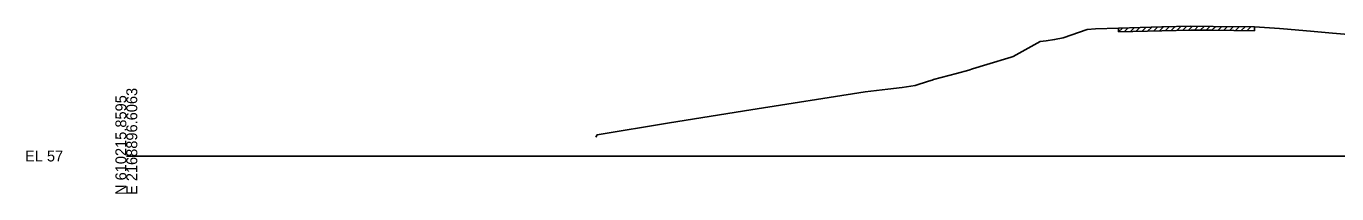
# Model space of a CAD drawing. Extents: x -26 to 6803, y -10 to 19606.
# Drawn here: x 1974.3 to 2310.6, y 12490.3 to 12533.3 of the extents above; entities that cross this region are included whole.
import ezdxf

# ---------------------------------------------------------------- set-up
doc = ezdxf.new("R2010")
doc.units = 0
for name, color, linetype in [('RD_GPK_XS_Cell', 7, 'Continuous'), ('RD_XS_ExGround', 7, 'Continuous'), ('RD_XS_ExPaveRet', 7, 'Continuous')]:
    doc.layers.add(name, color=color, linetype=linetype)

msp = doc.modelspace()

# ---------------------------------------------------------------- linework, layer by layer
at = {"layer": 'RD_GPK_XS_Cell'}
msp.add_line((2000, 12500), (2400, 12500), dxfattribs=at)
at = {"layer": 'RD_XS_ExGround'}
msp.add_lwpolyline([(2120.47, 12504.83), (2120.81, 12505.42), (2139.34, 12508.51), (2160.28, 12511.84), (2189.59, 12516.47), (2195.37, 12517.13), (2199.05, 12517.58), (2202.42, 12518.13), (2205.8, 12519.18), (2206.74, 12519.46), (2207.12, 12519.62), (2213.04, 12521.16), (2216.17, 12521.99), (2217.09, 12522.39), (2220.84, 12523.47), (2227.09, 12525.37), (2227.58, 12525.54), (2234.47, 12529.38), (2236.06, 12529.59), (2238.19, 12529.89), (2240.38, 12530.33), (2246.57, 12532.44), (2248.73, 12532.6), (2254.58, 12532.82), (2265.74, 12533.11), (2273.14, 12533.3), (2278.86, 12533.25), (2289.48, 12533.14), (2295.95, 12532.7), (2297.93, 12532.55), (2304.79, 12531.92), (2309.52, 12531.5), (2314.62, 12531.09)], dxfattribs=at)
at = {"layer": 'RD_XS_ExPaveRet'}
for p, q in [((2254.58, 12531.82), (2255.61, 12532.84)), ((2254.58, 12531.82), (2254.58, 12532.82)), ((2254.58, 12531.82), (2265.74, 12532.11)), ((2256.08, 12531.86), (2257.11, 12532.88)), ((2257.58, 12531.9), (2258.61, 12532.92)), ((2259.08, 12531.94), (2260.11, 12532.96)), ((2260.58, 12531.98), (2261.61, 12533)), ((2262.08, 12532.01), (2263.11, 12533.04)), ((2263.58, 12532.05), (2264.61, 12533.08)), ((2265.08, 12532.09), (2266.11, 12533.12)), ((2265.74, 12532.11), (2273.14, 12532.3)), ((2266.58, 12532.13), (2267.61, 12533.16)), ((2268.08, 12532.17), (2269.11, 12533.2)), ((2269.58, 12532.21), (2270.61, 12533.24)), ((2271.08, 12532.25), (2272.11, 12533.28)), ((2272.58, 12532.29), (2273.59, 12533.3)), ((2273.14, 12532.3), (2278.86, 12532.25)), ((2274.08, 12532.29), (2275.07, 12533.28)), ((2275.58, 12532.28), (2276.57, 12533.27)), ((2277.08, 12532.27), (2278.07, 12533.26)), ((2278.58, 12532.25), (2279.57, 12533.24)), ((2278.86, 12532.25), (2289.48, 12532.14)), ((2280.08, 12532.24), (2281.07, 12533.23)), ((2281.58, 12532.22), (2282.57, 12533.21)), ((2283.08, 12532.21), (2284.07, 12533.19)), ((2284.58, 12532.19), (2285.57, 12533.18)), ((2286.08, 12532.17), (2287.07, 12533.16)), ((2287.58, 12532.16), (2288.57, 12533.15)), ((2289.48, 12533.14), (2289.48, 12532.14))]:
    msp.add_line(p, q, dxfattribs=at)

# ---------------------------------------------------------------- texts
at = {"layer": 'RD_GPK_XS_Cell'}
for s, p in [('E 2168896.6063', (2002.8, 12490)), ('N 610215.8595', (2000, 12490))]:
    msp.add_text(s, height=2.8, rotation=90, dxfattribs=at).set_placement(p)
msp.add_text('EL 57', height=2.8, dxfattribs=at).set_placement((1974, 12498.6))

doc.saveas('drawing.dxf')
